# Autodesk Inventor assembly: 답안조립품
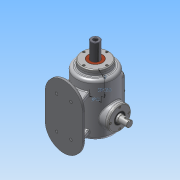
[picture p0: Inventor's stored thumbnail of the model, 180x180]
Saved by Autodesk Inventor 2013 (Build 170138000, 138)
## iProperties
Created: 2016-08
Part Number: 답안조립품
Document SubType Name: Assembly
Designer: Administrator
Author: Administrator
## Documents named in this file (16)
- C:\Users\Administrator\Desktop\360808V1007\답안조립품.iam
- C:\Users\Administrator\Desktop\360808V1007\본체.ipt
- C:\Users\Administrator\Desktop\360808V1007\플레이트.ipt
- C:\Users\Administrator\Desktop\360808V1007\부시.ipt
- C:\Users\Administrator\Desktop\360808V1007\슬라이드 커버.ipt
- C:\Users\Administrator\Desktop\360808V1007\슬라이드.ipt
- C:\Users\Administrator\Desktop\360808V1007\편심축.ipt
- C:\Users\Administrator\Desktop\360808V1007\가변스프링.ipt
- C:\Users\Administrator\Desktop\360808V1007\베어링 6205.ipt
- 베어링 6205.ipt
- C:\Users\Administrator\Desktop\360808V1007\축 커버.ipt
- C:\Users\Administrator\Desktop\360808V1007\오일실.ipt
- 오일실.ipt
- C:\Users\Administrator\Desktop\360808V1007\볼트 M4x0.7.ipt
- C:\Users\Administrator\Desktop\360808V1007\상부커버.ipt
- C:\Users\Administrator\Desktop\360808V1007\육각머리볼트 M4.ipt
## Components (14 placed, 3 different names)
1. 플레이트:1
2. 가변스프링:1
3. M4x0.7:1
4. M4x0.7:2
5. M4x0.7:3
6. M4x0.7:4
7. M4x0.7:5
8. M4x0.7:6
9. M4x0.7:7
10. M4x0.7:8
11. M4x0.7:11
12. M4x0.7:9
13. M4x0.7:12
14. M4x0.7:13
